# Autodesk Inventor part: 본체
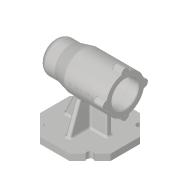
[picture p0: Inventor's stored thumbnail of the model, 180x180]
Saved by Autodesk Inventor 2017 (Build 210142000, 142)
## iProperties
Created: 2019-12
Part Number: 본체
Material: 알루미늄 6061
Document SubType Name: Modeling
Designer: 5-08-le
Density: 2.7 g/cm^3
Appearance: 알루미늄 - 평지
Mass: 725.805 g
Surface Area: 714.68 cm^2
Volume: 268.817 cm^3
Author: 5-08-le
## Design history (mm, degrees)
sketch "스케치1" dims "d0" = 112
  geometry: L1 (56, -23.196)-(23.196, -56); L2 (23.196, -56)-(-23.196, -56); L3 (-23.196, -56)-(-56, -23.196); L4 (-56, -23.196)-(-56, 23.196); L5 (-56, 23.196)-(-23.196, 56); L6 (-23.196, 56)-(23.196, 56); L7 (23.196, 56)-(56, 23.196); L8 (56, 23.196)-(56, -23.196); C1 r 5 at (39.598, 39.598); C2 r 5 at (39.598, -39.598); C3 r 5 at (-39.598, -39.598); C4 r 5 at (-39.598, 39.598); 4 further points
  constraints: 16 end point, 5 midpoint, 4 centre point, 3 equal radius, 2 coincident, 1 horizontal alignment, 19 other
  dimensions: "d1" = 10 diameter of C1
extrude "돌출1" new body sketch "스케치1" distance "d2" = 10; taper "d3" = 0 deg
extrude "돌출2" cut sketch "스케치1" distance "d4" = 10; taper "d5" = 0 deg
sketch "스케치2"
  geometry: L1 (56, 80)-(-11, 80); L2 (-11, 80)-(-11, 110); L3 (-11, 110)-(56, 110); L4 (56, 110)-(56, 80); L5 (-11, 80)-(-56, 80); L6 (-56, 80)-(-56, 105); L7 (-56, 105)-(-11, 105); L8 (-11, 105)-(-11, 80); L9 (56, 0)-(56, 10) reference; L10 (56, 0)-(43.134, 0) reference; L11 (-11, 110)-(-31, 105); 2 further points
  constraints: 18 end point, 4 parallel, 2 horizontal, 2 perpendicular, 1 collinear, 1 midpoint, 1 point on line
  dimensions: "d6" = 80 distance from line of L10 L1.start; "d7" = 112 distance between parallel lines of L6 L4; "d8" = 45 distance between parallel lines of L6 L2; "d9" = 60 diameter of L3 L1; "d10" = 50 diameter of L7 L5; "d77" = 25 distance from line of L11.end L6
revolve "회전1" sketch "스케치2" stored, may be unused: angle "d11" = 90 deg
sketch "스케치9"
  geometry: L1 (-38, 10)-(-16.012, 57.154); L2 (-16.012, 57.154)-(31, 57.154); L3 (-34.598, 0)-(-34.598, 10) reference; L4 (31, 57.154)-(31, 10); L5 (31, 10)-(-38, 10); L6 (34.598, 10)-(43.134, 10) reference; L7 (56, 0)-(56, 10) reference; L8 (-56, 0)-(-56, 10) reference; L9 (-43.134, 10)-(-34.598, 10) reference; 3 further points
  constraints: 8 end point, 1 collinear, 1 perpendicular, 1 vertical
  dimensions: "d50" = 25 distance between parallel lines of L4 L7; "d51" = 18 distance from line of L1.start L8; "d52" = 115 deg angle of L9 L1
extrude "돌출5" join sketch "스케치9" stored distance "d53" = 8; taper "d54" = 0 deg
sketch "스케치10"
  geometry: L1 (10, 36)-(46.824, 22.597); L2 (0, 56)-(10, 56) reference; L3 (10, 43.134)-(10, 56) reference; L4 (10, 43.134)-(10, 34.598) reference; 2 further points
  constraints: 2 end point, 1 point on line
  dimensions: "d55" = 20 distance from line of L1.start L2; "d56" = 110 deg angle of L3 L1
feature "리브1" sketch "스케치10" dims "d57" = 1, "d58" = 8, "d59" = 0, "d60" = 0, "d61" = 1, "d62" = 1
sketch "스케치3"
  geometry: L1 (56, 80)-(41, 80); L2 (41, 80)-(41, 101); L3 (41, 101)-(56, 101); L4 (56, 101)-(56, 80); L5 (41, 80)-(-13, 80); L6 (-13, 80)-(-13, 101); L7 (-10, 104)-(38, 104); L8 (41, 101)-(41, 80); L9 (-13, 80)-(-25, 80); L10 (-25, 80)-(-25, 100.7); L11 (-24.7, 101)-(-13, 101); L12 (-13, 101)-(-13, 80); L13 (-25, 80)-(-43, 80); L14 (-43, 80)-(-43, 97.2); L15 (-42.7, 97.5)-(-25, 97.5); L16 (-25, 97.5)-(-25, 80); L17 (-47, 80)-(-50, 80); L18 (-50, 80)-(-50, 90.5); L19 (-47, 90.5)-(-47, 80); L20 (-43, 80)-(-47, 80); L21 (-47, 80)-(-47, 95.7); L22 (-46.7, 96)-(-43, 96); L23 (-43, 96)-(-43, 80); L24 (43.134, 0)-(56, 0) reference; L25 (-47, 90.5)-(-50, 90.5); L26 (56, 50)-(56, 110) reference; A1 r 3 centre (38, 101) between (41, 101) and (38, 104); A2 r 3 centre (-10, 101) between (-10, 104) and (-13, 101); A3 r 0.3 centre (-46.7, 95.7) between (-46.7, 96) and (-47, 95.7); A4 r 0.3 centre (-42.7, 97.2) between (-42.7, 97.5) and (-43, 97.2); A5 r 0.3 centre (-24.7, 100.7) between (-24.7, 101) and (-25, 100.7); 6 further points
  constraints: 48 end point, 12 point on line, 11 parallel, 10 point on circle, 10 tangent, 7 horizontal, 6 perpendicular, 5 centre point, 3 equal radius, 1 collinear
  dimensions: "d12" = 80 distance from line of L24 L1.start; "d13" = 42 diameter of L3 L1; "d14" = 15 distance of L2.end L3.end; "d15" = 48 diameter of L7 L5; "d16" = 54 distance of point (-13, 104) point (41, 104); "d17" = 42 diameter of L11 L9; "d18" = 12 distance of point (-25, 101) L11.end; "d19" = 21 diameter of L25 L17; "d20" = 3 distance of L19.start L18.end; "d21" = 32 diameter of L22 L20; "d22" = 4 distance of point (-47, 96) L22.end; "d23" = 18 distance of point (-43, 97.5) L15.end; "d24" = 35 diameter of L15 L13; "d25" = 3 radius of A1; "d26" = 0.3 radius of A3
revolve "회전2" sketch "스케치3" stored, may be unused: angle "d27" = 90 deg
sketch "스케치4"
  geometry: C1 r 6 at (0, 30); 2 further points
  constraints: 1 centre point, 1 vertical alignment, 1 other
  dimensions: "d28" = 12 diameter of C1
extrude "돌출3" join sketch "스케치4" distance "d29" = 16; taper "d30" = 0 deg
sketch "스케치5"
  geometry: A1 r 6 centre (0, 0) between (5.97, -0.6) and (-5.97, -0.6) reference; A2 r 6 centre (-30, -30) between (-29.4, -24.03) and (-29.4, -35.97) reference; A3 r 6 centre (0, -60) between (-5.97, -59.4) and (5.97, -59.4) reference; A4 r 6 centre (30, -30) between (29.4, -35.97) and (29.4, -24.03) reference; 1 further point
hole "구멍1" sketch "스케치5" at (30, -30), (0, -60), (0, 0), (-30, -30) diameter "d34" = 3.242; stored, may be unused: countersink angle "d38" = 90 deg, drill point angle "d40" = 118 deg; dims "d35" = 8, "d36" = 4, "d37" = 2, "d39" = 11
fillet "모깎기1" dims "d63" = 3
chamfer "모따기1" distance "d64" = 1; stored, may be unused: second distance "d65" = 2, angle "d66" = 45 deg
fillet "모깎기2" dims "d67" = 10
fillet "모깎기3" dims "d68" = 3
fillet "모깎기4" dims "d69" = 3
fillet "모깎기5" dims "d70" = 3
fillet "모깎기6" dims "d71" = 1
sketch "스케치11"
  geometry: L1 (59.258, 0)-(46.392, 0) reference; L2 (79.196, 86.771)-(79.196, 109.226) reference; 2 further points
  constraints: 1 other
  dimensions: "d73" = 80 distance from line of point (38.196, 80) L1; "d74" = 41 distance from line of point (38.196, 80) L2
feature "엠보싱1" sketch "스케치11" dims "d6" = 80, "d7" = 112, "d8" = 45, "d9" = 60, "d10" = 50, "d75" = 0.5, "d76" = 0, "d77" = 25
fillet "모깎기8" dims "d78" = 3
fillet "모깎기9" dims "d79" = 3
fillet "모깎기10" dims "d80" = 3
node "솔리드1"
mirror "미러1"
pattern_circular "원형 패턴1" dims angle "d32" = 360 deg
